(* Logix 5000 project; controller CompactLogix vendor 1 type 14 code 65 rev 16.20; software revision 16.03 *)

TASK MainTask (continuous, watchdog 500 ms) : MainProgram

MODULES
   Controller : vendor 1 type 14 code 65 (CompactLogixL35Controller 0, rev 16.20)
      LocalENB : 1769-L35E Ethernet Port (CompactLogixL35Ethernet 1, rev 16.3)
      Local : CompactBus (CompactVirtualAdapter 3, rev 16.3, Input RPI 5 ms)
         MNETC : 1769-MODULE (Compact 1, rev 1.1, Output RPI 2 ms)
END_MODULES

TYPE MNetCBlockStats :   // This object is used to store the block transfer statistics for the MVI69-MNet module.
STRUCT
   Read : INT;   // Total number of read block transfers
   Write : INT;   // Total number of write block transfers
   Parse : INT;   // Total number of blocks parsed
   Event : INT;   // Total number of event blocks received
   Cmd : INT;   // Total number of command blocks received
   Err : INT;   // Total number of block transfer errors
END_STRUCT
END_TYPE

TYPE MnetCCmdControl :
STRUCT
   CmdCntReqClientID : INT;   // Block5000 Client IDentification by Index number 0 to 29
   CmdCntReqCMDqty : INT;   // Block5000 command quantity
   CmdCntReqCMDindex : INT[16];   // Contains index in the command list for the 1st command to be entered into Command queue
   WriteCmdBits : INT[30];   // This is for 30 Clients with 16 commands each.
   CmdBitsTrigger : BOOL;   // Activates the Selected Write Command Bits
END_STRUCT
END_TYPE

TYPE MNetCCONFIG :
STRUCT
   BlockTransferSize : INT;   // Determines Register quantity to move across the Backplane
END_STRUCT
END_TYPE

TYPE MNetCConnectionInput :
STRUCT
   Data : INT[62];   // Block Transfer Array Size [62] or [122] or [242]
END_STRUCT
END_TYPE

TYPE MNetCConnectionOutput :
STRUCT
   Data : INT[61];   // Block Transfer Array Size [61] or [121] or [241]
END_STRUCT
END_TYPE

TYPE MNetCCONTROL :
STRUCT
   BootTimer : TIMER;
   ColdBoot : BOOL;   // Hardware reset of the Module
   WarmBoot : BOOL;   // Configuration data reset in the Module.
   EventCmd : MNetCEventCmd[1];
   EventCmdTrigger : BOOL;
   EventCmdPending : BOOL;   // Halts rung until Module is ready.
   CmdControl : MnetCCmdControl;
   CmdControlPending : BOOL;   // Halts rung until Module is ready.
   CmdControlTrigger : BOOL;
   IPAdressControl : MNetCIPAddress;
   CmdBitPending : BOOL;   // Halts rung until Module is ready.
   CmdBitTrigger : BOOL;
END_STRUCT
END_TYPE

TYPE MNetCDATA :
STRUCT
   ReadData : INT[480];
   WriteData : INT[480];
END_STRUCT
END_TYPE

TYPE MNetCEventCmd :   // Data structure to use for Event message generation.
STRUCT
   IP0 : INT;   // TCP/IP-0 address for MNETC module
   IP1 : INT;   // TCP/IP-1 address for MNETC module
   IP2 : INT;   // TCP/IP-2 address for MNETC module
   IP3 : INT;   // TCP/IP-3 address for MNETC module
   ServPort : INT;   // TCP Service Port number (0-65535), 502 for MBAP, 2000 for MNET
   Node : INT;   // Modbus slave node address (0 to 247)
   DBAddress : INT;   // Module internal database to use with message
   Count : INT;   // Register or data point count
   Swap : INT;   // Swap code to use with functions 3 and 4
   Function : INT;   // Modbus function code for message
   Address : INT;   // Address to interface with in device
   EvntCmdClientID : INT;   // Block2000 Client IDentification by Index number 0 to 29
END_STRUCT
END_TYPE

TYPE MNetCInitOutData :   // Used to bring the Module into a known state after a restart operation.
STRUCT
   InitOutBlkIDLim : INT;   // Block Index Limit for ReadData size of the array
END_STRUCT
END_TYPE

TYPE MNetCIPAddress :   // Dynamicaly Alterable TCP/IP address for MNETC module. Block 9990 and 9991
STRUCT
   GetIPAddress : BOOL;   // Gets IP address
   GetIP : INT[4];   // Get IP
   GetIPAddressPending : BOOL;   // Halts rung until Module is ready.
   SetIPAddress : BOOL;   // Sets IP address
   SetIP : INT[4];   // Set IP
   SetIPAddrPending : BOOL;   // Halts rung until Module is ready.
   WriteIPAddressAck : INT[4];   // Module's response to Setting IP Address
END_STRUCT
END_TYPE

TYPE MNetCModuleDef :
STRUCT
   CONFIG : MNetCCONFIG;
   DATA : MNetCDATA;
   CONTROL : MNetCCONTROL;
   STATUS : MNetCSTATUS;
   UTIL : MNetCUTIL;
END_STRUCT
END_TYPE

TYPE MNetCPortStats :   // This object is used to store the port statistics for an MVI69-MNet port.
STRUCT
   CmdReq : INT;   // Total number of command list requests sent
   CmdResp : INT;   // Total number of command list responses received
   CmdErr : INT;   // Total number of command list errors
   Requests : INT;   // Total number of requests for port
   Responses : INT;   // Total number of responses for port
   ErrSent : INT;   // Total number of errors sent
   ErrRec : INT;   // Total number of errors received
   CfgErrWord : INT;   // Configuration Error Word
   CurErr : INT;   // Current Error code
   LastErr : INT;   // Last recorded error code
END_STRUCT
END_TYPE

TYPE MNetCSTATUS :   // This status data is returned on each read block and can be used to detect proper module operation.
STRUCT
   PassCnt : INT;   // Program cycle counter
   Block : MNetCBlockStats;   // Block transfer statistics
   MnetServer : MNetCPortStats;   // MNet server status data
   MBAPServer : MNetCPortStats;   // MBAP server status data
   StatReqClientID : INT;   // Block3000 Client IDentification by Index number 0 to 29
   CmdBits : INT[30];
   ClientStats : MNetCPortStats[30];   // Client status data
   ClientStatsPending : BOOL;   // Halts rung until Module is ready.
   ClientStatsTrigger : BOOL;   // Get Client Status
   CmdErrorList : INT[16];   // Cmd Error List
END_STRUCT
END_TYPE

TYPE MNetCUTIL :
STRUCT
   ReadDataSizeGet : INT;   // Gets ReadData Array Length.
   WriteDataSizeGet : INT;   // Gets WriteData Array Length.
   ReadDataBlkCount : INT;   // holds the value of the Block Counts of the Read Data Array.
   WriteDataBlkCount : INT;   // holds the value of the Block Counts of the Write Data Array.
   RBTSremainder : INT;   // The remainder of the 60, 120 or 240 block to transfer.
   WBTSremainder : INT;   // The remainder of the 60, 120 or 240 block to transfer.
   LastRead : INT;   // Index of last read block
   LastWrite : INT;   // Index of last write block
   BlockIndex : INT;   // Computed block offset for data table
   StatusIndex : INT;   // Computed block offset for status data
   InitOutputData : MNetCInitOutData;
END_STRUCT
END_TYPE

ADD_ON_INSTRUCTION AOI69MNETC   (* revision 1.3 *)
// Add On instruction interface between the CompactLogix backplane and the MVI69-MNETC module.
// Revision note:
// v1.3 - Initialize output data block now supports flexible read and write data array sizing.
VAR_IN_OUT
   Connection_Input : MNetCConnectionInput; {required}
   Connection_Output : MNetCConnectionOutput; {required}
   MNETC : MNetCModuleDef; {required}
END_VAR

ROUTINE Logic   (* ladder *)
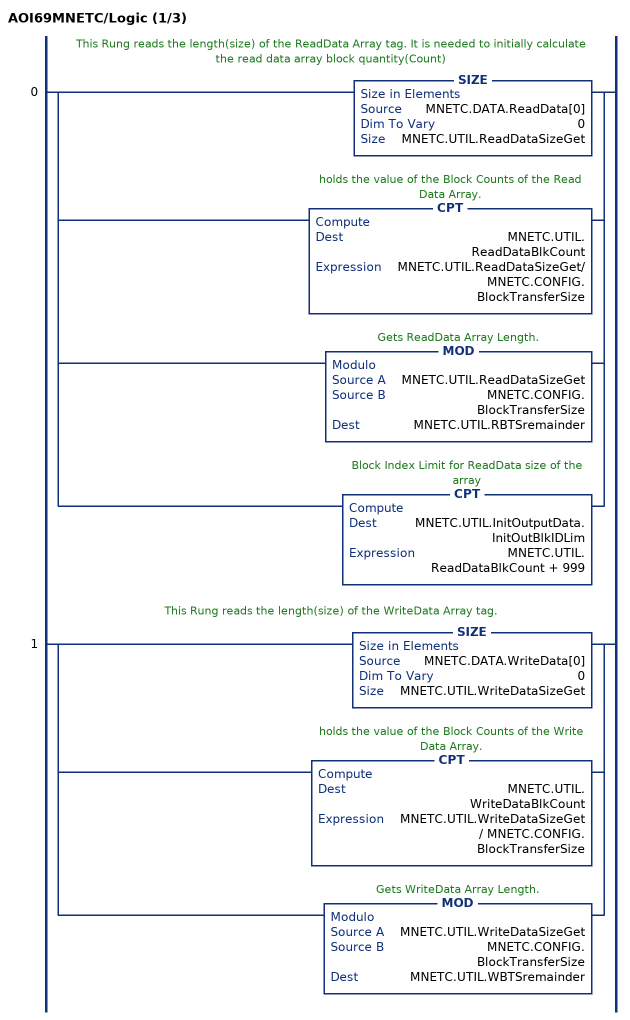
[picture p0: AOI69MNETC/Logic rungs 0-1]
   // This Rung reads the length(size) of the ReadData Array tag. It is needed to initially calculate the read data array block quantity(Count)
   0: [SIZE(MNETC.DATA.ReadData[0],0,MNETC.UTIL.ReadDataSizeGet) ,CPT(MNETC.UTIL.ReadDataBlkCount,MNETC.UTIL.ReadDataSizeGet/MNETC.CONFIG.BlockTransferSize) ,MOD(MNETC.UTIL.ReadDataSizeGet,MNETC.CONFIG.BlockTransferSize,MNETC.UTIL.RBTSremainder) ,CPT(MNETC.UTIL.InitOutputData.InitOutBlkIDLim,MNETC.UTIL.ReadDataBlkCount + 999) ];
   // This Rung reads the length(size) of the WriteData Array tag.
   1: [SIZE(MNETC.DATA.WriteData[0],0,MNETC.UTIL.WriteDataSizeGet) ,CPT(MNETC.UTIL.WriteDataBlkCount,MNETC.UTIL.WriteDataSizeGet / MNETC.CONFIG.BlockTransferSize) ,MOD(MNETC.UTIL.WriteDataSizeGet,MNETC.CONFIG.BlockTransferSize,MNETC.UTIL.WBTSremainder) ];
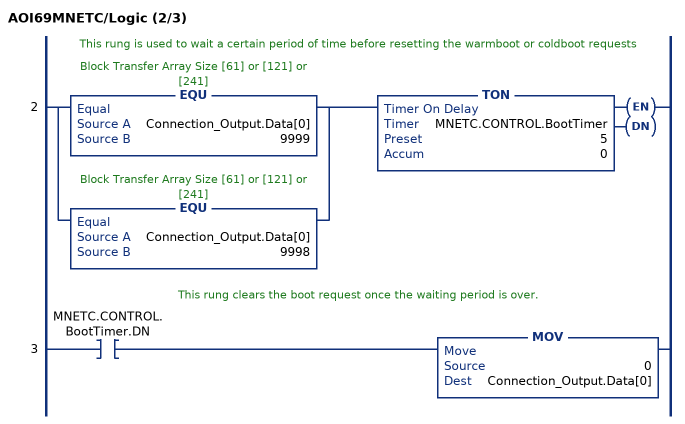
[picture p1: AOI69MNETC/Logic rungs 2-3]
   // This rung is used to wait a certain period of time before resetting the warmboot or coldboot requests
   2: [EQU(Connection_Output.Data[0],9999) ,EQU(Connection_Output.Data[0],9998) ]TON(MNETC.CONTROL.BootTimer,5,0);
   // This rung clears the boot request once the waiting period is over.
   3: XIC(MNETC.CONTROL.BootTimer.DN)MOV(0,Connection_Output.Data[0]);
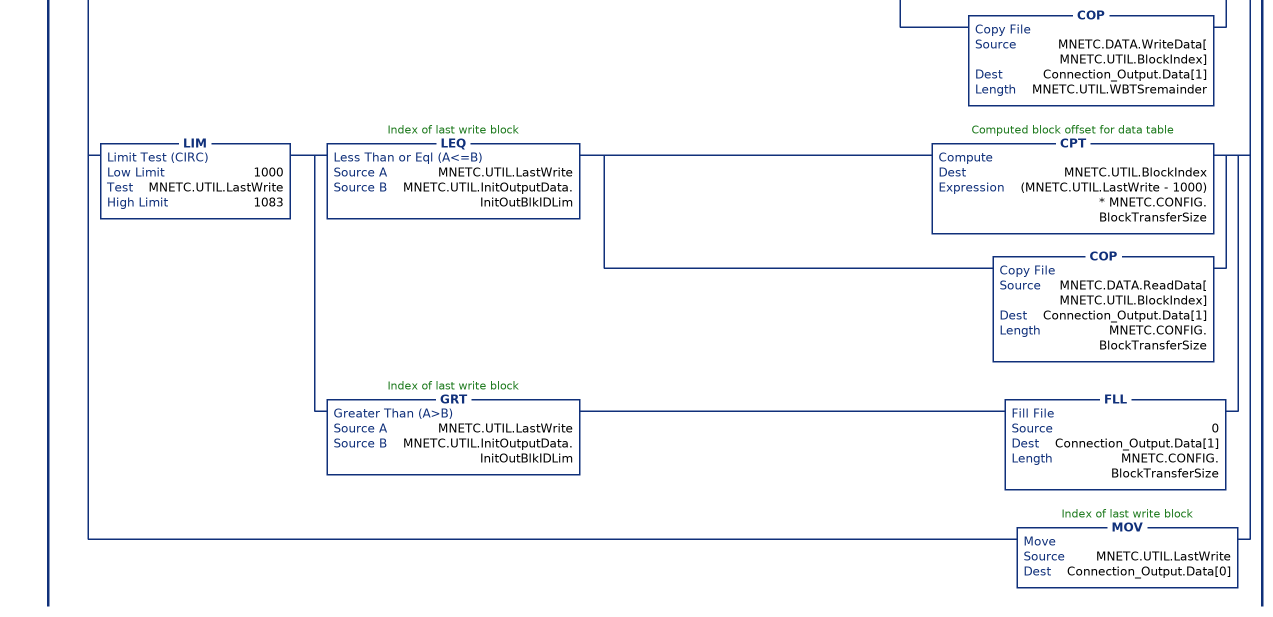
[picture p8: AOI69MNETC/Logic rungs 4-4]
   // This rung is used to check for a new read block from the MVI56-MNETC module in slot 1.  If new data is available, the LastRead and word[0] will not be equal.  This will force the program to call the ReadData subroutine to process the new data received.  After the new data is placed in the Modbus Data Table, the program will send new data to the module using the WriteData subroutine.
   4: NEQ(Connection_Input.Data[0],MNETC.UTIL.LastRead)[MOV(Connection_Input.Data[0],MNETC.UTIL.LastRead) ,GEQ(MNETC.UTIL.LastRead,1) [LEQ(MNETC.UTIL.LastRead,MNETC.UTIL.ReadDataBlkCount) [CPT(MNETC.UTIL.BlockIndex,(MNETC.UTIL.LastRead-1)*MNETC.CONFIG.BlockTransferSize) ,COP(Connection_Input.Data[2],MNETC.DATA.ReadData[MNETC.UTIL.BlockIndex],MNETC.CONFIG.BlockTransferSize) ] ,CMP(MNETC.UTIL.LastRead - MNETC.UTIL.ReadDataBlkCount = 1) GRT(MNETC.UTIL.RBTSremainder,0) [CPT(MNETC.UTIL.BlockIndex,(MNETC.UTIL.LastRead - 1) * MNETC.CONFIG.BlockTransferSize) ,COP(Connection_Input.Data[2],MNETC.DATA.ReadData[MNETC.UTIL.BlockIndex],MNETC.UTIL.RBTSremainder) ] ] ,[EQU(-1,MNETC.UTIL.LastRead) ,EQU(0,MNETC.UTIL.LastRead) ] [COP(Connection_Input.Data[2],MNETC.STATUS.PassCnt,1) ,COP(Connection_Input.Data[3],MNETC.STATUS.Block.Read,6) ,COP(Connection_Input.Data[9],MNETC.STATUS.CmdBits[0],30) ] ,LIM(2000,MNETC.UTIL.LastRead,2029) EQU(Connection_Input.Data[2],1) OTU(MNETC.CONTROL.EventCmdPending) ,LIM(3000,MNETC.UTIL.LastRead,3029) [COP(Connection_Input.Data[2],MNETC.STATUS.ClientStats[MNETC.STATUS.StatReqClientID].CmdReq,10) ,COP(Connection_Input.Data[12],MNETC.STATUS.CmdErrorList[0],16) ,OTU(MNETC.STATUS.ClientStatsPending) ] ,LIM(5000,MNETC.UTIL.LastRead,5016) LIM(1,Connection_Input.Data[2],16) OTU(MNETC.CONTROL.CmdControlPending) ,EQU(MNETC.UTIL.LastRead,9990) [COP(Connection_Input.Data[2],MNETC.CONTROL.IPAdressControl.WriteIPAddressAck[0],4) ,OTU(MNETC.CONTROL.IPAdressControl.SetIPAddrPending) ] ,EQU(MNETC.UTIL.LastRead,9991) [COP(Connection_Input.Data[2],MNETC.CONTROL.IPAdressControl.GetIP[0],4) ,OTU(MNETC.CONTROL.IPAdressControl.GetIPAddressPending) ] ,MOV(Connection_Input.Data[1],MNETC.UTIL.LastWrite) ,LIM(1000,MNETC.UTIL.LastWrite,1008) [CPT(MNETC.UTIL.BlockIndex,(MNETC.UTIL.LastWrite - 1000) * MNETC.CONFIG.BlockTransferSize) ,COP(MNETC.DATA.ReadData[MNETC.UTIL.BlockIndex],Connection_Output.Data[1],MNETC.CONFIG.BlockTransferSize) ] ,XIC(MNETC.CONTROL.WarmBoot) [MOV(9998,MNETC.UTIL.LastWrite) ,OTU(MNETC.CONTROL.WarmBoot) ] ,XIC(MNETC.CONTROL.ColdBoot) [MOV(9999,MNETC.UTIL.LastWrite) ,OTU(MNETC.CONTROL.ColdBoot) ] ,XIC(MNETC.CONTROL.EventCmdTrigger) XIO(MNETC.CONTROL.EventCmdPending) [COP(MNETC.CONTROL.EventCmd[0].IP0,Connection_Output.Data[1],11) ,LIM(0,MNETC.CONTROL.EventCmd[0].EvntCmdClientID,29) ADD(2000,MNETC.CONTROL.EventCmd[0].EvntCmdClientID,MNETC.UTIL.LastWrite) ,OTU(MNETC.CONTROL.EventCmdTrigger) ,OTL(MNETC.CONTROL.EventCmdPending) ] ,XIC(MNETC.STATUS.ClientStatsTrigger) XIO(MNETC.STATUS.ClientStatsPending) [LIM(0,MNETC.STATUS.StatReqClientID,29) ADD(3000,MNETC.STATUS.StatReqClientID,MNETC.UTIL.LastWrite) ,OTL(MNETC.STATUS.ClientStatsPending) ,OTU(MNETC.STATUS.ClientStatsTrigger) ] ,XIC(MNETC.CONTROL.CmdControlTrigger) XIO(MNETC.CONTROL.CmdControlPending) [LIM(0,MNETC.CONTROL.CmdControl.CmdCntReqClientID,29) MOV(MNETC.CONTROL.CmdControl.CmdCntReqClientID,Connection_Output.Data[1]) ,COP(MNETC.CONTROL.CmdControl.CmdCntReqCMDindex[0],Connection_Output.Data[2],16) ,LIM(1,MNETC.CONTROL.CmdControl.CmdCntReqCMDqty,16) ADD(5000,MNETC.CONTROL.CmdControl.CmdCntReqCMDqty,MNETC.UTIL.LastWrite) ,OTL(MNETC.CONTROL.CmdControlPending) ,OTU(MNETC.CONTROL.CmdControlTrigger) ] ,[EQU(MNETC.UTIL.LastWrite,0) ,EQU(MNETC.UTIL.LastWrite,-1) ,XIC(MNETC.CONTROL.CmdControl.CmdBitsTrigger) MOV(0,MNETC.UTIL.LastWrite) ] [COP(MNETC.CONTROL.CmdControl.WriteCmdBits[0],Connection_Output.Data[1],30) ,OTU(MNETC.CONTROL.CmdControl.CmdBitsTrigger) ] ,XIC(MNETC.CONTROL.IPAdressControl.SetIPAddress) XIO(MNETC.CONTROL.IPAdressControl.SetIPAddrPending) [MOV(9990,MNETC.UTIL.LastWrite) ,COP(MNETC.CONTROL.IPAdressControl.SetIP[0],Connection_Output.Data[1],4) ,OTL(MNETC.CONTROL.IPAdressControl.SetIPAddrPending) ,OTU(MNETC.CONTROL.IPAdressControl.SetIPAddress) ] ,XIC(MNETC.CONTROL.IPAdressControl.GetIPAddress) XIO(MNETC.CONTROL.IPAdressControl.GetIPAddressPending) [MOV(9991,MNETC.UTIL.LastWrite) ,OTL(MNETC.CONTROL.IPAdressControl.GetIPAddressPending) ,OTU(MNETC.CONTROL.IPAdressControl.GetIPAddress) ] ,GEQ(MNETC.UTIL.LastWrite,1) [LEQ(MNETC.UTIL.LastWrite,MNETC.UTIL.WriteDataBlkCount) [CPT(MNETC.UTIL.BlockIndex,(MNETC.UTIL.LastWrite - 1) * MNETC.CONFIG.BlockTransferSize) ,COP(MNETC.DATA.WriteData[MNETC.UTIL.BlockIndex],Connection_Output.Data[1],MNETC.CONFIG.BlockTransferSize) ] ,CMP(MNETC.UTIL.LastWrite - MNETC.UTIL.WriteDataBlkCount = 1) GRT(MNETC.UTIL.WBTSremainder,0) [CPT(MNETC.UTIL.BlockIndex,(MNETC.UTIL.LastWrite - 1)* MNETC.CONFIG.BlockTransferSize) ,COP(MNETC.DATA.WriteData[MNETC.UTIL.BlockIndex],Connection_Output.Data[1],MNETC.UTIL.WBTSremainder) ] ] ,LIM(1000,MNETC.UTIL.LastWrite,1083) [LEQ(MNETC.UTIL.LastWrite,MNETC.UTIL.InitOutputData.InitOutBlkIDLim) [CPT(MNETC.UTIL.BlockIndex,(MNETC.UTIL.LastWrite - 1000) * MNETC.CONFIG.BlockTransferSize) ,COP(MNETC.DATA.ReadData[MNETC.UTIL.BlockIndex],Connection_Output.Data[1],MNETC.CONFIG.BlockTransferSize) ] ,GRT(MNETC.UTIL.LastWrite,MNETC.UTIL.InitOutputData.InitOutBlkIDLim) FLL(0,Connection_Output.Data[1],MNETC.CONFIG.BlockTransferSize) ] ,MOV(MNETC.UTIL.LastWrite,Connection_Output.Data[0]) ];
END_ROUTINE
END_ADD_ON_INSTRUCTION

VAR_GLOBAL   (* controller tags *)
   AOI69MNETC : AOI69MNETC;
   Connection_Input : MNetCConnectionInput := (Data[0] := 4, Data[1] := 4);
   Connection_Output : MNetCConnectionOutput := (Data[0] := 4);
   MNetC : MNetCModuleDef;
        .BP.LASTREAD   // this tag receives Block ID data from the last scan.
        .GETIPADDRESS   // Gets the IP address from the Module.
        .SETIPADDRESS   // Sets the IP address for the Module
END_VAR

PROGRAM MainProgram   (* main routine MainRoutine *)

ROUTINE MainRoutine   (* ladder *)
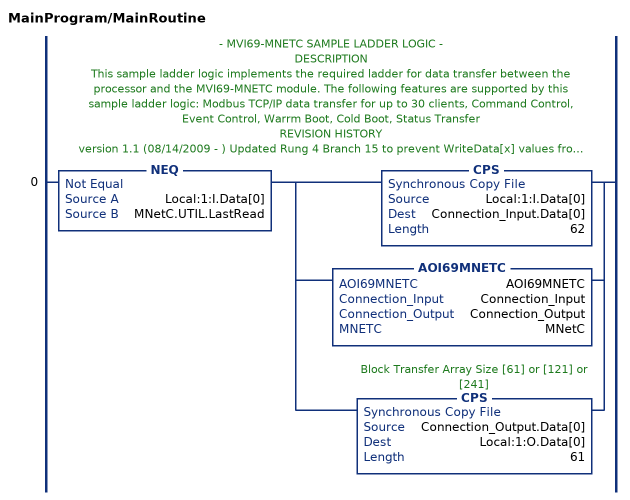
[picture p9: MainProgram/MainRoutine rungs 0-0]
   // - MVI69-MNETC SAMPLE LADDER LOGIC -
   // DESCRIPTION
   // This sample ladder logic implements the required ladder for data transfer between the processor and the MVI69-MNETC module. The following features are supported by this sample ladder logic: Modbus TCP/IP data transfer for up to 30 clients, Command Control, Event Control, Warrm Boot, Cold Boot, Status Transfer
   // REVISION HISTORY
   // version 1.1 (08/14/2009 - ) Updated Rung 4 Branch 15 to prevent WriteData[x] values from being applied as WriteCmdBits data when Block ID=0.
   // version 1.0. (08/29/2008) - Release
   0: NEQ(Local:1:I.Data[0],MNetC.UTIL.LastRead)[CPS(Local:1:I.Data[0],Connection_Input.Data[0],62) ,AOI69MNETC(AOI69MNETC,Connection_Input,Connection_Output,MNetC) ,CPS(Connection_Output.Data[0],Local:1:O.Data[0],61) ];
END_ROUTINE
END_PROGRAM
